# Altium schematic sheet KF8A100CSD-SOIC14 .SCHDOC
size A4
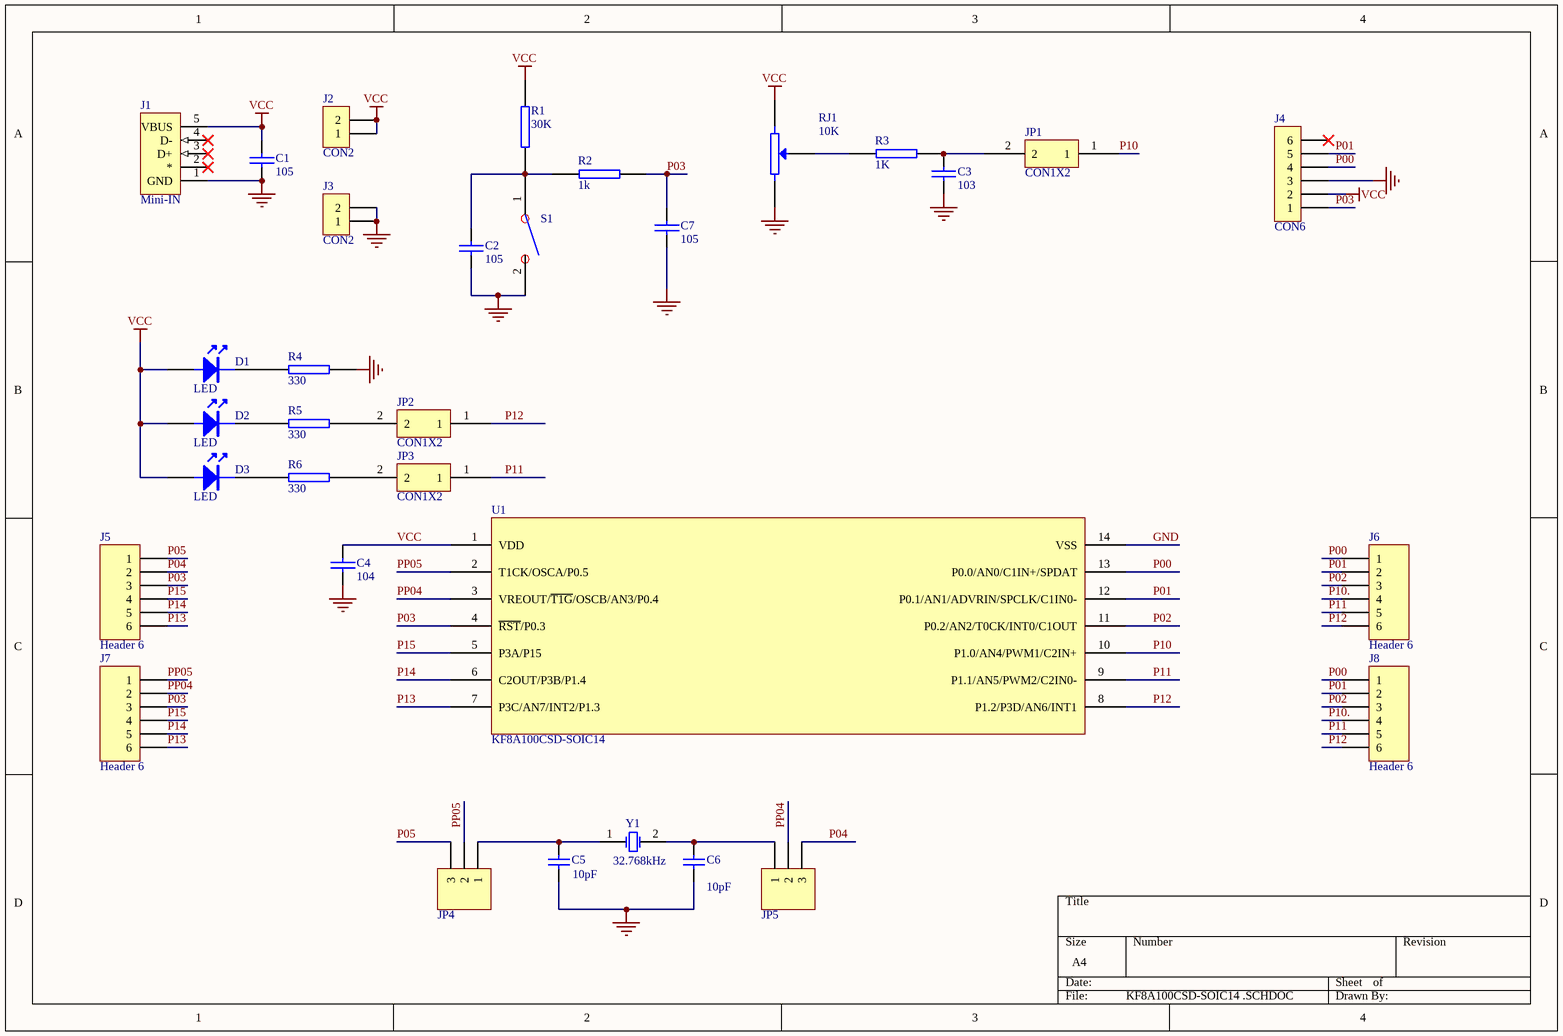
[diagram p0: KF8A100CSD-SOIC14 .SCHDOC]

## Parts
C1  105  [0805]
C2  105  [0805]
C3  103  [0805]
C4  104  [0805]
C5  value 10pF  [0805]
C6  value 10pF  [0805]
C7  105  [0805]
D1  LED  [LED0805]
D2  LED  [LED0805]
D3  LED  [LED0805]
J1  Mini-IN  [MINI B USB]
J2  CON2  [SIP2]
J3  CON2  [SIP2]
J4  CON6  [ICSP887]
J5  Header 6  [HDR1X6]
J6  Header 6  [HDR1X6]
J7  Header 6  [HDR1X6]
J8  Header 6  [HDR1X6]
JP1  CON1X2  [SIP2]
JP2  CON1X2  [SIP2]
JP3  CON1X2  [SIP2]
JP4  (no value)  [HDR1X3]
JP5  (no value)  [HDR1X3]
R1  30K  [0805]
R2  1k  [0805]
R3  1K  [0805]
R4  330  [0805]
R5  330  [0805]
R6  330  [0805]
RJ1  10K  [VR5H]
S1  (no value)  [SW_SOP]
U1  KF8A100CSD-SOIC14  [SO14]
Y1  32.768kHz  [BCY-W2/D3.1]

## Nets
GND: C1.2 C2.2 C3.2 C4.2 C5.1 C6.1 C7.2 J1.1(GND) J3.1 J3.2 J4.3 R4.1 RJ1.2 S1.2 U1.14(VSS)
VCC: C1.1 C4.1 D1.A D2.A D3.A J1.5(VBUS) J2.1 J2.2 J4.2 R1.2 RJ1.1 U1.1(VDD)
P00: J4.4 J6.1 J8.1 U1.13(P0.0/AN0/C1IN+/SPDAT)
P01: J4.5 J6.2 J8.2 U1.12(P0.1/AN1/ADVRIN/SPCLK/C1IN0-)
P02: J6.3 J8.3 U1.11(P0.2/AN2/T0CK/INT0/C1OUT)
P03: C7.1 J4.1 J5.3 J7.3 R2.1 U1.4(~{RST}/P0.3)
P04: J5.2 JP5.3
P05: J5.1 JP4.3
P10: JP1.1 U1.10(P1.0/AN4/PWM1/C2IN+)
P10.: J6.4 J8.4
P11: J6.5 J8.5 JP3.1 U1.9(P1.1/AN5/PWM2/C2IN0-)
P12: J6.6 J8.6 JP2.1 U1.8(P1.2/P3D/AN6/INT1)
P13: J5.6 J7.6 U1.7(P3C/AN7/INT2/P1.3)
P14: J5.5 J7.5 U1.6(C2OUT/P3B/P1.4)
P15: J5.4 J7.4 U1.5(P3A/P15)
PP04: J7.2 JP5.2 U1.3(VREOUT/~{T1G}/OSCB/AN3/P0.4)
PP05: J7.1 JP4.2 U1.2(T1CK/OSCA/P0.5)
NetC2_1: C2.1 R1.1 R2.2 S1.1
NetC3_1: C3.1 JP1.2 R3.1
NetC5_2: C5.2 JP4.1 Y1.1(OSC1)
NetC6_2: C6.2 JP5.1 Y1.2(OSC2)
NetD1_K: D1.K R4.2
NetD2_K: D2.K R5.2
NetD3_K: D3.K R6.2
NetJP2_2: JP2.2 R5.1
NetJP3_2: JP3.2 R6.1
NetR3_2: R3.2 RJ1.3(W)

Not connected (* = marked no-connect by the designer): J1 2(*)* 3(D+)* 4(D-)*; J4 6*

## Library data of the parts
C1-C4 C7 = CAP: Capacitor
C5 C6 = Cap: Capacitor
J1 = USB-5: USB 1.1, Right Angle, Thru-Hole, Reverse Type, Receptacle, 4 Position, Black
J2 J3 = CON2: Connector
J4 = CON6: Connector
J5-J8 = Header 6: Header, 6-Pin
JP1-JP3 = CON1X2: J?
JP4 JP5 = Header 3: Header, 3-Pin
R1-R6 = RES2
RJ1 = POT2: Potentiometer
S1 = KEY_X
U1 = KF8F3130-SOIC14
Y1 = XTAL: Crystal Oscillator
